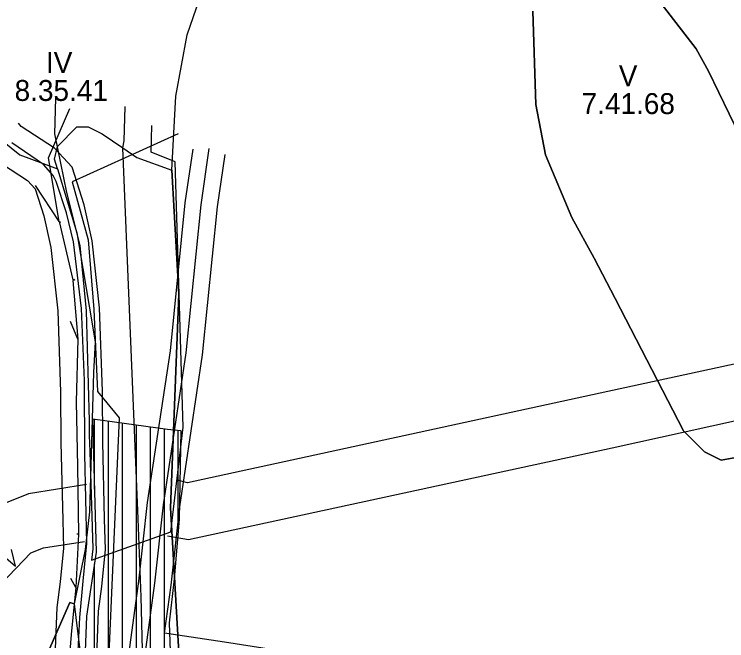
# Model space of a CAD drawing. Extents: x -694504 to -690518, y -983661 to -978958.
# Drawn here: x -693779 to -693268, y -981032 to -980583 of the extents above; entities that cross this region are included whole.
import ezdxf

# ---------------------------------------------------------------- set-up
doc = ezdxf.new("R2010")
doc.units = 0
for name, color, linetype in [('BPEJ', 7, 'Continuous'), ('kabelové a venkovní rozvody telefonu', 7, 'Continuous'), ('lokální biocentra', 7, 'Continuous'), ('nadregionální biokoridor', 7, 'Continuous'), ('ochranné pásmo silnic', 7, 'Continuous'), ('ochranné pásmo vedení', 7, 'Continuous'), ('odvodněné pozemky', 7, 'Continuous'), ('třídy přednosti v ochraně ZP', 7, 'Continuous'), ('vedení NN', 7, 'Continuous'), ('vedení VN 35kV', 7, 'Continuous'), ('vodovodní řad', 7, 'Continuous')]:
    doc.layers.add(name, color=color, linetype=linetype)

msp = doc.modelspace()

# ---------------------------------------------------------------- linework, layer by layer
at = {"layer": 'BPEJ'}
for points in [[(-693259.4, -980669.81), (-693281.4, -980623.81), (-693290.4, -980607.81), (-693350.4, -980529.81)], [(-693350.4, -980529.81), (-693290.4, -980607.81), (-693281.4, -980623.81), (-693259.4, -980669.81)], [(-693425.4, -981570.81), (-693452.4, -981468.81), (-693453.4, -981448.81), (-693458.4, -981426.81), (-693478.4, -981371.81), (-693507.4, -981323.81), (-693561.4, -981255.81), (-693572.4, -981243.81), (-693599.4, -981215.81), (-693634.4, -981174.81), (-693647.4, -981147.81), (-693657.4, -981106.81), (-693667.4, -980936.81), (-693661.4, -980783.81), (-693666.4, -980694.81), (-693663.4, -980641.81), (-693655.4, -980597.81), (-693644.4, -980565.81)], [(-693407.4, -980580.81), (-693405.4, -980647.81), (-693398.4, -980683.81), (-693379.4, -980728.81), (-693363.4, -980757.81), (-693348.4, -980786.81), (-693299.4, -980881.81), (-693284.4, -980896.81), (-693272.4, -980902.81), (-693251.4, -980898.81)], [(-693251.4, -980898.81), (-693272.4, -980902.81), (-693284.4, -980896.81), (-693299.4, -980881.81), (-693348.4, -980786.81), (-693363.4, -980757.81), (-693379.4, -980728.81), (-693398.4, -980683.81), (-693405.4, -980647.81), (-693407.4, -980580.81)], [(-693701.4, -980678.81), (-693700.4, -980673.81), (-693699.83, -980649.17)], [(-693800.4, -980663.81), (-693775.4, -980683.81), (-693748.4, -980693.81), (-693748.4, -980693.81), (-693734.4, -980739.81), (-693721.4, -980817.81), (-693722.4, -980839.81), (-693725.4, -980939.81), (-693728.4, -980966.81), (-693736.4, -981005.81), (-693739.4, -981004.81), (-693779.4, -981095.81)], [(-693748.4, -980693.81), (-693750.4, -980686.81), (-693748.4, -980677.81), (-693734.4, -980663.81), (-693726.4, -980663.81), (-693716.4, -980668.81), (-693701.4, -980678.81)], [(-693687.4, -981038.81), (-693688.4, -981000.81), (-693690.4, -980944.81), (-693701.4, -980678.81), (-693691.4, -980685.81), (-693666.4, -980694.81), (-693666.4, -980694.81), (-693661.4, -980783.81), (-693667.4, -980936.81), (-693657.4, -981106.81)], [(-693812.4, -980949.81), (-693778.4, -980978.81), (-693781.4, -980966.81)], [(-693779.4, -981095.81), (-693739.4, -981004.81), (-693736.4, -981005.81), (-693736.4, -981005.81), (-693731.4, -981046.81), (-693734.4, -981100.81), (-693744.4, -981171.81), (-693736.4, -981198.81), (-693713.4, -981239.81), (-693640.4, -981356.81), (-693612.4, -981381.81), (-693545.4, -981423.81), (-693530.4, -981435.81), (-693517.4, -981446.81), (-693492.4, -981482.81), (-693477.4, -981518.81)]]:
    msp.add_lwpolyline(points, dxfattribs=at)
at = {"layer": 'kabelové a venkovní rozvody telefonu'}
msp.add_lwpolyline([(-693733.44, -981039.51), (-693732.24, -981015.49), (-693729.9, -980989.43), (-693727.26, -980962.44), (-693728.73, -980898.42), (-693729.02, -980845.68), (-693731.07, -980793.99), (-693735.48, -980758.02), (-693736.94, -980746.18), (-693741.9, -980725.46), (-693749.24, -980702.85), (-693751.34, -980698.65), (-693758.45, -980690.65), (-693781.03, -980675.1)], dxfattribs=at)
at = {"layer": 'lokální biocentra'}
msp.add_lwpolyline([(-693749.7, -980643.13), (-693750.44, -980668.84), (-693741.82, -980710.92), (-693732.35, -980748.78), (-693727.83, -980795.68), (-693725.71, -980874.43), (-693725.65, -980885.15), (-693725.1, -980896.42), (-693722.99, -980966.35), (-693723.98, -980974.34), (-693666.95, -980954.17), (-693658.09, -980879.08), (-693664.03, -980688.72), (-693681.19, -980681.94), (-693680.75, -980662.78)], dxfattribs=at)
at = {"layer": 'nadregionální biokoridor'}
for points in [[(-692976.88, -980387.74), (-693001, -980423.8), (-693051.69, -980447.88), (-693086.28, -980481.45), (-693108.83, -980506.94), (-693122.82, -980518.78), (-693146.81, -980554.13), (-693146.81, -980575.87), (-693138.39, -980628.27), (-693165.64, -980702.13), (-693190.13, -980705.8), (-693196.33, -980766.6), (-693215.28, -980804.51), (-693215.47, -980802.6), (-693218.38, -980803.25), (-693225.6, -980825.71), (-693359.08, -980854.74), (-693655.15, -980918.88), (-693662.19, -980917.18), (-693662.19, -980917.18), (-693662.19, -980917.18)], [(-693669.34, -980956.96), (-693654.47, -980959.66), (-693350.54, -980893.81), (-693225.99, -980866.33)], [(-693727.49, -980920.29), (-693769.15, -980926.87), (-693790.24, -980935.31), (-693816.91, -980963.08), (-693833.13, -980978.45), (-693853.04, -980987.5), (-693889.48, -981008.93), (-693904.33, -981021.66), (-693904.33, -981021.66), (-693904.33, -981021.66)], [(-693897.02, -981066.18), (-693897.02, -981066.18), (-693879.29, -981052.88), (-693866.14, -981041.61), (-693834.57, -981023.05), (-693810.48, -981012.1), (-693788.71, -980991.47), (-693767.37, -980969.24), (-693758.47, -980965.68), (-693728.89, -980961.01)]]:
    msp.add_lwpolyline(points, dxfattribs=at)
at = {"layer": 'ochranné pásmo silnic'}
for points in [[(-693721.15, -981069.05), (-693718.85, -981010.9), (-693716.59, -980993.32), (-693713.89, -980966.87), (-693714.56, -980945.06), (-693715.85, -980889.69), (-693716.1, -980853.26), (-693718.19, -980793.47), (-693723.49, -980745.48), (-693729.1, -980719.64), (-693737.83, -980692.56), (-693750.53, -980678.96), (-693774.41, -980663.5), (-693776.32, -980661.01)], [(-693795.02, -980685.9), (-693769.93, -980702.14), (-693764.33, -980708.14), (-693758.11, -980727.44), (-693753.14, -980750.32), (-693748.14, -980795.64), (-693746.1, -980853.89), (-693745.84, -980890.15), (-693744.55, -980945.87), (-693743.93, -980965.81), (-693746.39, -980989.88), (-693748.77, -981008.39), (-693751.11, -981067.51)]]:
    msp.add_lwpolyline(points, dxfattribs=at)
at = {"layer": 'ochranné pásmo vedení'}
for points in [[(-693651.38, -980679.68), (-693656.92, -980718.26), (-693667.62, -980824.29), (-693683.91, -980933.2), (-693690.14, -980989.43), (-693696.37, -981035.22), (-693702.38, -981085.52), (-693708.34, -981136.78), (-693719.79, -981230.73), (-693726.09, -981276.83), (-693732.01, -981321.47), (-693748.76, -981419.32), (-693764.35, -981508.69), (-693803.41, -981569.49), (-693844.21, -981633.2), (-693885.67, -981697.92), (-693913.63, -981741.57), (-693930.34, -981735.73), (-694180.58, -981650.28), (-694223.83, -981635.39)], [(-692739.96, -981204.97), (-692834.02, -981187.35), (-692924.48, -981170.45), (-693008.63, -981155.22), (-693098.05, -981139.02), (-693191.42, -981122.13), (-693284.2, -981099.61), (-693356.17, -981083.19), (-693481.9, -981059.5), (-693556.87, -981044.56), (-693628.51, -981033.31), (-693671.51, -981026.82), (-693666.81, -980992.3), (-693660.61, -980936.24), (-693644.3, -980827.21), (-693633.59, -980721.11), (-693628.19, -980683.5)]]:
    msp.add_lwpolyline(points, dxfattribs=at)
at = {"layer": 'odvodněné pozemky'}
for p, q in [((-693721.68, -980923.41), (-693721.68, -980873.36)), ((-693711.68, -981263.65), (-693711.68, -980874.73)), ((-693701.68, -981279.21), (-693701.68, -980876.11)), ((-693691.68, -981299.58), (-693691.68, -980877.48)), ((-693681.68, -981301.17), (-693681.68, -980878.85)), ((-693671.68, -981298.81), (-693671.68, -980880.23)), ((-693661.68, -980953.23), (-693661.68, -980881.25)), ((-693721.68, -981248.09), (-693721.68, -980977.08))]:
    msp.add_line(p, q, dxfattribs=at)
msp.add_lwpolyline([(-693753.06, -981190.72), (-693750.43, -981177.55), (-693736.74, -981122.79), (-693732.01, -981103.3), (-693729.37, -981070.66), (-693727.27, -981014.53), (-693720.43, -980968.71), (-693723.07, -980873.17), (-693669.39, -980880.54), (-693659.93, -980881.41), (-693660.98, -980945.13), (-693664.67, -980987.78), (-693668.35, -981019.38), (-693664.7, -981120.28)], dxfattribs=at)
at = {"layer": 'vedení NN'}
for points in [[(-693747.2, -980731.53), (-693754.69, -980685.95), (-693739.36, -980650.56)], [(-693747.2, -980731.53), (-693764.04, -980705.85)], [(-693747.2, -980731.53), (-693737.38, -980773.51)], [(-693747.2, -980731.53), (-693746.15, -980732.15)], [(-693736.1, -980773.4), (-693736.15, -980773.2), (-693737.38, -980773.51)], [(-693736.1, -980773.4), (-693736.06, -980773.59), (-693737.28, -980773.9)], [(-693737.28, -980773.9), (-693733.8, -980816.08)], [(-693733.8, -980816.08), (-693738.99, -980803.33)], [(-693733.8, -980816.08), (-693734.86, -980860.94), (-693734, -980907.34), (-693733.26, -980955.83)], [(-693733.26, -980955.83), (-693735.16, -980993.96)], [(-693733.26, -980955.83), (-693734.52, -980955.74)], [(-693735.16, -980993.96), (-693738.74, -980987.54)], [(-693735.16, -980993.96), (-693738.54, -981027.71)], [(-693738.54, -981027.71), (-693742.2, -981072.5)]]:
    msp.add_lwpolyline(points, dxfattribs=at)
at = {"layer": 'vedení VN 35kV'}
msp.add_lwpolyline([(-694329.39, -982435.38), (-694307.8, -982344.86), (-694238.38, -982244.76), (-694180.67, -982160.33), (-694116.67, -982065.53), (-694056.9, -981976.86), (-693977.95, -981861.54), (-693915.76, -981766.68), (-693875.77, -981704.26), (-693834.32, -981639.54), (-693793.52, -981575.83), (-693753.18, -981513.05), (-693737.18, -981421.32), (-693720.39, -981323.23), (-693714.44, -981278.4), (-693708.14, -981232.24), (-693696.67, -981138.17), (-693690.71, -981086.89), (-693684.71, -981036.71), (-693678.48, -980990.86), (-693672.26, -980934.72), (-693655.96, -980825.75), (-693645.25, -980719.68), (-693639.46, -980679.34)], dxfattribs=at)
at = {"layer": 'vodovodní řad'}
msp.add_lwpolyline([(-693661.76, -980668.83), (-693737.77, -980703.2), (-693726.34, -980744.78), (-693722.18, -980794.68), (-693719.58, -980853.41), (-693704.2, -980872.35), (-693718.24, -981194.42), (-693675.78, -981276.1), (-693635.08, -981331.54), (-693568.57, -981321.09), (-693526.95, -981316.12), (-693463.62, -981321.99)], dxfattribs=at)

# ---------------------------------------------------------------- texts
at = {"layer": 'třídy přednosti v ochraně ZP'}
for s, p in [('IV', (-693756.62, -980625.16)), ('V', (-693345.84, -980634.58)), ('8.35.41', (-693779.07, -980645.16)), ('7.41.68', (-693372.53, -980654.58))]:
    msp.add_text(s, height=15, dxfattribs=at).set_placement(p)

doc.saveas('drawing.dxf')
